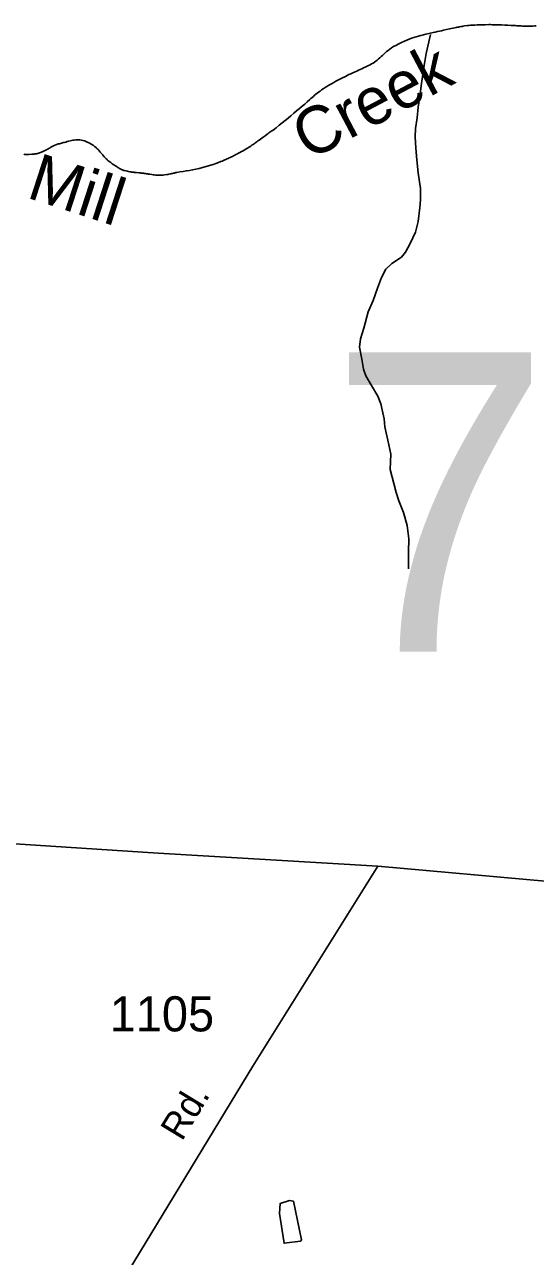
# Model space of a CAD drawing. Extents: x 2206922 to 2357709, y 510027 to 673830.
# Drawn here: x 2236284 to 2238102, y 575657 to 580043 of the extents above; entities that cross this region are included whole.
import ezdxf

# ---------------------------------------------------------------- set-up
doc = ezdxf.new("R2010")
doc.units = 0
for name, color, linetype in [('Exist Boundary Political CountyLine', 7, 'Continuous'), ('Exist Hydrographic Misc Water Feature', 7, 'Continuous'), ('Exist Hydrographic River Shore Label', 7, 'Continuous'), ('Exist Road Secondary Structure Standard Bridge Number Label', 7, 'Continuous'), ('Exist Road Secondary Type 51 Attributed', 7, 'Continuous'), ('Exist Road Secondary Type 51 Label', 7, 'Continuous'), ('Exist Road Secondary Type 51 Number Label', 7, 'Continuous')]:
    doc.layers.add(name, color=color, linetype=linetype)

msp = doc.modelspace()

# ---------------------------------------------------------------- linework, layer by layer
at = {"layer": 'Exist Boundary Political CountyLine'}
for points in [[(2238105.3, 580038.8), (2238099, 580038), (2238093.3, 580037.4), (2238087.5, 580037.1), (2238082, 580036.9), (2238076.8, 580036.8), (2238071.5, 580036.9), (2238066.6, 580037), (2238061.5, 580037.2), (2238056.5, 580037.5), (2238051.4, 580038), (2238046.5, 580038.3), (2238041.6, 580038.6), (2238036.2, 580038.9), (2238031.3, 580039.2), (2238026, 580039.5), (2238020.5, 580039.8), (2238015.3, 580040.1), (2238004.3, 580040.6), (2237998.7, 580040.8), (2237993, 580041), (2237981.5, 580041.4), (2237975.6, 580041.6), (2237969.4, 580041.8), (2237962, 580042.1), (2237955, 580042.3), (2237948.5, 580042.4), (2237941.9, 580042.6), (2237935.8, 580042.6), (2237923.3, 580042.5), (2237916.7, 580042.4), (2237909.9, 580042.2), (2237902.8, 580042), (2237895.2, 580041.5), (2237886.8, 580041.1), (2237877.7, 580040.6), (2237871.6, 580040.2), (2237865.4, 580039.7), (2237859.9, 580039.2), (2237850.1, 580038), (2237845.3, 580037.2), (2237840.8, 580036.5), (2237836.5, 580035.7), (2237832.2, 580034.9), (2237827.9, 580034.1), (2237824, 580033.2), (2237819.7, 580032.3), (2237815.8, 580031.4), (2237809.3, 580030.1), (2237796.3, 580027.2), (2237775.2, 580022.7), (2237768, 580021.1), (2237760.7, 580019.5), (2237753.3, 580017.9), (2237745.7, 580016.2), (2237738.1, 580014.5), (2237722.5, 580011), (2237712.5, 580008.7), (2237703.2, 580006.5), (2237694.2, 580004.3), (2237685.8, 580002), (2237677.4, 579999.6), (2237669.4, 579997)], [(2237669.4, 579997), (2237661.2, 579994.2), (2237653, 579991), (2237644.2, 579987.6), (2237635.6, 579983.6), (2237625.9, 579979.2), (2237616.1, 579974.2), (2237605.2, 579968.6), (2237597.4, 579964.2), (2237590.3, 579959.8), (2237583.7, 579955.4), (2237577.8, 579950.9), (2237572.2, 579946.4), (2237567.1, 579941.9), (2237562, 579937.4), (2237557.2, 579933), (2237552.7, 579928.7), (2237548, 579924.5), (2237543.5, 579920.4), (2237538.8, 579916.4), (2237533.7, 579912.6), (2237528.9, 579909.2), (2237524, 579906), (2237518.7, 579902.9), (2237513.6, 579900), (2237508, 579897), (2237496.6, 579891.4), (2237490.4, 579888.6), (2237484.5, 579885.8), (2237478.5, 579883.1), (2237472.1, 579880.3), (2237466.2, 579877.4), (2237460.1, 579874.6), (2237452.5, 579871), (2237445.3, 579867.7), (2237438.5, 579864.5), (2237432, 579861.4), (2237425.6, 579858.3), (2237412.7, 579851.9), (2237406.3, 579848.6), (2237399.2, 579844.9), (2237392, 579841.1), (2237384.2, 579836.7), (2237376.2, 579832.1), (2237367.2, 579827), (2237360, 579822.5), (2237353.2, 579818.3), (2237346.7, 579814.2), (2237340.9, 579810.1), (2237335.6, 579806.2), (2237330.3, 579802.3), (2237325.3, 579798.5), (2237320.8, 579794.7), (2237315.9, 579790.9), (2237311.8, 579787.1), (2237307.5, 579783.4), (2237303, 579779.6), (2237298.7, 579775.7), (2237290.1, 579768), (2237280.8, 579760), (2237271.4, 579752), (2237262, 579743.7), (2237251.9, 579735.3), (2237242.1, 579726.8), (2237231.8, 579718.3), (2237221.6, 579709.8), (2237210.9, 579701.2), (2237200.5, 579692.7), (2237189.8, 579684.1), (2237178.7, 579675.7), (2237168.1, 579667.3), (2237164.2, 579664.5), (2237160.7, 579661.8), (2237157.2, 579659.3), (2237153.7, 579656.9), (2237150.4, 579654.5), (2237147.3, 579652.1), (2237140.2, 579647.2), (2237136.5, 579644.6), (2237132.6, 579641.7), (2237128.3, 579638.8), (2237123.8, 579635.4), (2237118.8, 579631.7), (2237114.5, 579628.7), (2237110.8, 579625.9), (2237107, 579623.2), (2237103.7, 579620.8), (2237100.6, 579618.4), (2237097.5, 579616.2), (2237094.4, 579614.1), (2237091.8, 579612.1), (2237088.9, 579610.2), (2237083.6, 579606.6), (2237080.5, 579604.7), (2237077.8, 579602.9), (2237075, 579601.2), (2237065.9, 579595.9), (2237059.6, 579592.3), (2237056.3, 579590.6), (2237049.7, 579586.9)], [(2236572.8, 579566.2), (2236571.6, 579567.7), (2236568.5, 579570.9), (2236566.8, 579572.7), (2236565.2, 579574.6), (2236563.6, 579576.5), (2236561.7, 579578.6), (2236559.7, 579580.9), (2236557.4, 579583.3), (2236555.8, 579585.3), (2236553.9, 579587.2), (2236552.5, 579588.9), (2236551.3, 579590.6), (2236549.8, 579592.2), (2236548.8, 579593.7), (2236547.6, 579595.1), (2236546.3, 579596.5), (2236545.3, 579597.8), (2236542.6, 579600.4), (2236538.8, 579604.4), (2236536.9, 579605.9), (2236535.1, 579607.4), (2236533.2, 579608.8), (2236529.3, 579611.7), (2236527.3, 579613.1), (2236523.2, 579615.7), (2236521.3, 579616.9), (2236519.3, 579618.1), (2236517.2, 579619.1), (2236515.6, 579620.1), (2236512.9, 579621.4), (2236510.2, 579622.8), (2236507.6, 579624.1), (2236504.7, 579625.4), (2236501.8, 579626.6), (2236500, 579627.3), (2236496.7, 579628.5), (2236491.2, 579630.2), (2236486.1, 579631.4), (2236480.7, 579632.1), (2236475.8, 579632.5), (2236470.7, 579632.5), (2236465.8, 579632.3), (2236460.8, 579631.6), (2236455.7, 579630.8), (2236450.8, 579629.8), (2236445.7, 579628.6), (2236440.5, 579627.3), (2236435.2, 579626), (2236430.1, 579624.5), (2236426.2, 579623.5), (2236422.5, 579622.6), (2236418.8, 579621.6), (2236415.3, 579620.6), (2236411.4, 579619.6), (2236407.7, 579618.7), (2236404.2, 579617.7), (2236401, 579616.6), (2236397.7, 579615.6), (2236394.8, 579614.6), (2236389.3, 579612.4), (2236387, 579611.3), (2236384.8, 579610.1), (2236382.3, 579608.7), (2236379.8, 579607.3), (2236377.2, 579605.8), (2236374.5, 579604.2), (2236371.4, 579602.5), (2236368.6, 579600.7), (2236365.3, 579598.9), (2236361.8, 579597.1), (2236358.3, 579595.2), (2236354.4, 579593.5), (2236350.7, 579591.6), (2236346.8, 579589.8), (2236343.5, 579588.3), (2236340.3, 579587), (2236337.2, 579586), (2236334.3, 579585), (2236331.4, 579584.2), (2236328.8, 579583.5), (2236325.9, 579582.9), (2236323.2, 579582.4), (2236320.8, 579582.1), (2236317.9, 579581.7), (2236315.2, 579581.4), (2236312.6, 579581.1), (2236309.5, 579580.9), (2236299, 579580.4), (2236295.2, 579580.3), (2236291.7, 579580.4), (2236288, 579580.4), (2236284.5, 579580.7), (2236281.2, 579581)], [(2237049.7, 579586.9), (2237042.8, 579583.3), (2237039.5, 579581.5), (2237036, 579579.7), (2237031.7, 579577.5), (2237027.8, 579575.5), (2237023.7, 579573.5), (2237020, 579571.6), (2237015.9, 579569.8), (2237012.2, 579567.9), (2237008.3, 579566.1), (2237004.2, 579564.4), (2237000.3, 579562.5), (2236996, 579560.7), (2236991.5, 579558.8), (2236987, 579557), (2236982.1, 579555), (2236968.5, 579549.6), (2236955.2, 579544.9), (2236942.5, 579540.6), (2236929.8, 579536.9), (2236917.5, 579533.6), (2236905.6, 579530.6), (2236893.7, 579528), (2236882, 579525.6), (2236870.5, 579523.5), (2236859.2, 579521.6), (2236848, 579519.8), (2236836.7, 579518.1), (2236825.4, 579516.5), (2236822.5, 579515.7), (2236819.7, 579515), (2236816.8, 579514.3), (2236813.7, 579513.6), (2236810.7, 579512.8), (2236807.6, 579512.1), (2236804.5, 579511.4), (2236797.5, 579510), (2236794, 579509.4), (2236790.4, 579508.8), (2236782.1, 579507.7), (2236777, 579507.1), (2236772.1, 579506.7), (2236767, 579506.5), (2236762.5, 579506.5), (2236758, 579506.5), (2236753.9, 579506.8), (2236749.5, 579507.1), (2236745.4, 579507.5), (2236741.5, 579508), (2236737.2, 579508.6), (2236729.2, 579509.8), (2236725.3, 579510.5), (2236722.7, 579510.9), (2236720, 579511.3), (2236717.6, 579511.7), (2236714.7, 579512.1), (2236709.2, 579512.9), (2236706.7, 579513.2), (2236701.2, 579514), (2236698.5, 579514.3), (2236695.4, 579514.7), (2236690.1, 579515.3), (2236682.5, 579516), (2236675.5, 579516.7), (2236672.2, 579517), (2236668.8, 579517.4), (2236665.3, 579517.8), (2236661.8, 579518.3), (2236658.1, 579518.9), (2236654, 579519.7), (2236649.7, 579520.6), (2236645, 579521.7), (2236640, 579522.9), (2236637.2, 579523.7), (2236632.7, 579525.2), (2236630.4, 579526), (2236628.8, 579526.8), (2236626.7, 579527.6), (2236625.3, 579528.5), (2236623.4, 579529.4), (2236622, 579530.3), (2236620.6, 579531.2), (2236618.9, 579532.2), (2236617.5, 579533.1), (2236616.1, 579534.1), (2236613.2, 579535.9), (2236607.6, 579539.5), (2236605, 579541.4), (2236601.9, 579543.4), (2236596, 579547.4), (2236593.1, 579549.4), (2236590.2, 579551.6), (2236587.3, 579553.7), (2236581.8, 579557.9), (2236579.4, 579560.1), (2236577.5, 579561.6), (2236576.1, 579563.1), (2236574.2, 579564.6), (2236572.8, 579566.2)]]:
    msp.add_lwpolyline(points, dxfattribs=at)
at = {"layer": 'Exist Hydrographic Misc Water Feature'}
for points in [[(2237650.1, 578105.4), (2237649.9, 578165.4), (2237651.2, 578211.5), (2237645.2, 578259.4), (2237632.9, 578305.1), (2237616.5, 578347.3), (2237606.3, 578377.2), (2237597.8, 578408.9), (2237585.3, 578459.1), (2237587, 578512.7), (2237576.7, 578562.6), (2237570.4, 578588.6), (2237566.1, 578610.8), (2237563.8, 578638.7), (2237551.5, 578692.5), (2237541.3, 578720.3), (2237519.1, 578758.2), (2237498.4, 578792.1), (2237490.6, 578816), (2237484.7, 578851.8), (2237475.8, 578893.7), (2237479.5, 578923.9), (2237491.4, 578961.8), (2237506.6, 579020), (2237524.8, 579060.2), (2237540.2, 579104.1), (2237553.8, 579142.2), (2237569.8, 579172.3), (2237591.5, 579192.5), (2237624.9, 579214.7), (2237639.1, 579232.8), (2237656.7, 579263), (2237674.9, 579303.2), (2237684.2, 579341.1), (2237690.1, 579391.4), (2237693.4, 579419.3), (2237693.2, 579459.4), (2237685.2, 579515), (2237680.5, 579561.1), (2237676, 579603.1), (2237673.7, 579642.8), (2237675.4, 579673), (2237681.3, 579711), (2237685, 579749), (2237690.9, 579787), (2237696.1, 579833.3), (2237705.9, 579897.1), (2237713.7, 579939.3), (2237722.7, 579981.3), (2237728.9, 580007.2)], [(2237227.1, 575855.3), (2237240.6, 575853.2), (2237270, 575715.4), (2237266.1, 575711.5), (2237207.6, 575703.3), (2237191.2, 575809.2), (2237193.1, 575845), (2237227.1, 575855.3)]]:
    msp.add_lwpolyline(points, dxfattribs=at)
at = {"layer": 'Exist Road Secondary Type 51 Attributed'}
for points in [[(2237541.6, 577046.4), (2236759.3, 577092.1), (2235757.7, 577158.2), (2235337.3, 577184.9), (2235109.7, 577210.5), (2234988.8, 577227), (2234898.5, 577247.5), (2234777.6, 577286.5), (2234700.1, 577318.1), (2234627.8, 577349.4), (2234509.6, 577396.3), (2234288.9, 577486.6), (2233963.5, 577626.3), (2233907.5, 577645.5), (2233855.2, 577655), (2233835.1, 577655.1)], [(2241815.8, 577606), (2241686.6, 577572.1), (2241551.3, 577538.3), (2241388.3, 577501.4), (2241163.7, 577455.2), (2240899.2, 577390.6), (2240708.5, 577358.3), (2240511.7, 577309), (2240351.7, 577275.2), (2240247.2, 577250.5), (2240164.1, 577210.5), (2240038, 577161.3), (2239868.9, 577090.5), (2239665.9, 577007.4), (2239496.7, 576945.9), (2239413.7, 576930.5), (2239346, 576915.1), (2239287.6, 576909), (2239235.3, 576905.9), (2239164.5, 576905.9), (2239001.5, 576918.2), (2238758.5, 576936.7), (2237541.6, 577046.4)], [(2237541.6, 577046.4), (2237096.6, 576334.5), (2236656.5, 575608.8)]]:
    msp.add_lwpolyline(points, dxfattribs=at)

# ---------------------------------------------------------------- texts
at = {"layer": 'Exist Hydrographic River Shore Label'}
for s, rotation, p in [('Creek', 27.8655, (2237295, 579557)), ('Mill', 342.0283, (2236286.3, 579428.1))]:
    msp.add_text(s, height=167.32, rotation=rotation, dxfattribs=at).set_placement(p)
at = {"layer": 'Exist Road Secondary Structure Standard Bridge Number Label'}
msp.add_text('77', height=1066.27, dxfattribs=at).set_placement((2237365.1, 577809.4))
at = {"layer": 'Exist Road Secondary Type 51 Label'}
msp.add_text('Rd.', height=95, rotation=58.6982, dxfattribs=at).set_placement((2236843.7, 576063.8))
at = {"layer": 'Exist Road Secondary Type 51 Number Label'}
msp.add_text('1105', height=125, dxfattribs=at).set_placement((2236586.6, 576457.9))

doc.saveas('drawing.dxf')
